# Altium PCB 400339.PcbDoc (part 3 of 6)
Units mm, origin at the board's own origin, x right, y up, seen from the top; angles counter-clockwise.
Board outline 146 x 63.5 mm, 4 copper layers (Top Layer, Mid-Layer 1, Mid-Layer 2, Bottom Layer), stack 1.505 mm thick; 400 components, 261 nets, 1523 pads, 1938 vias.
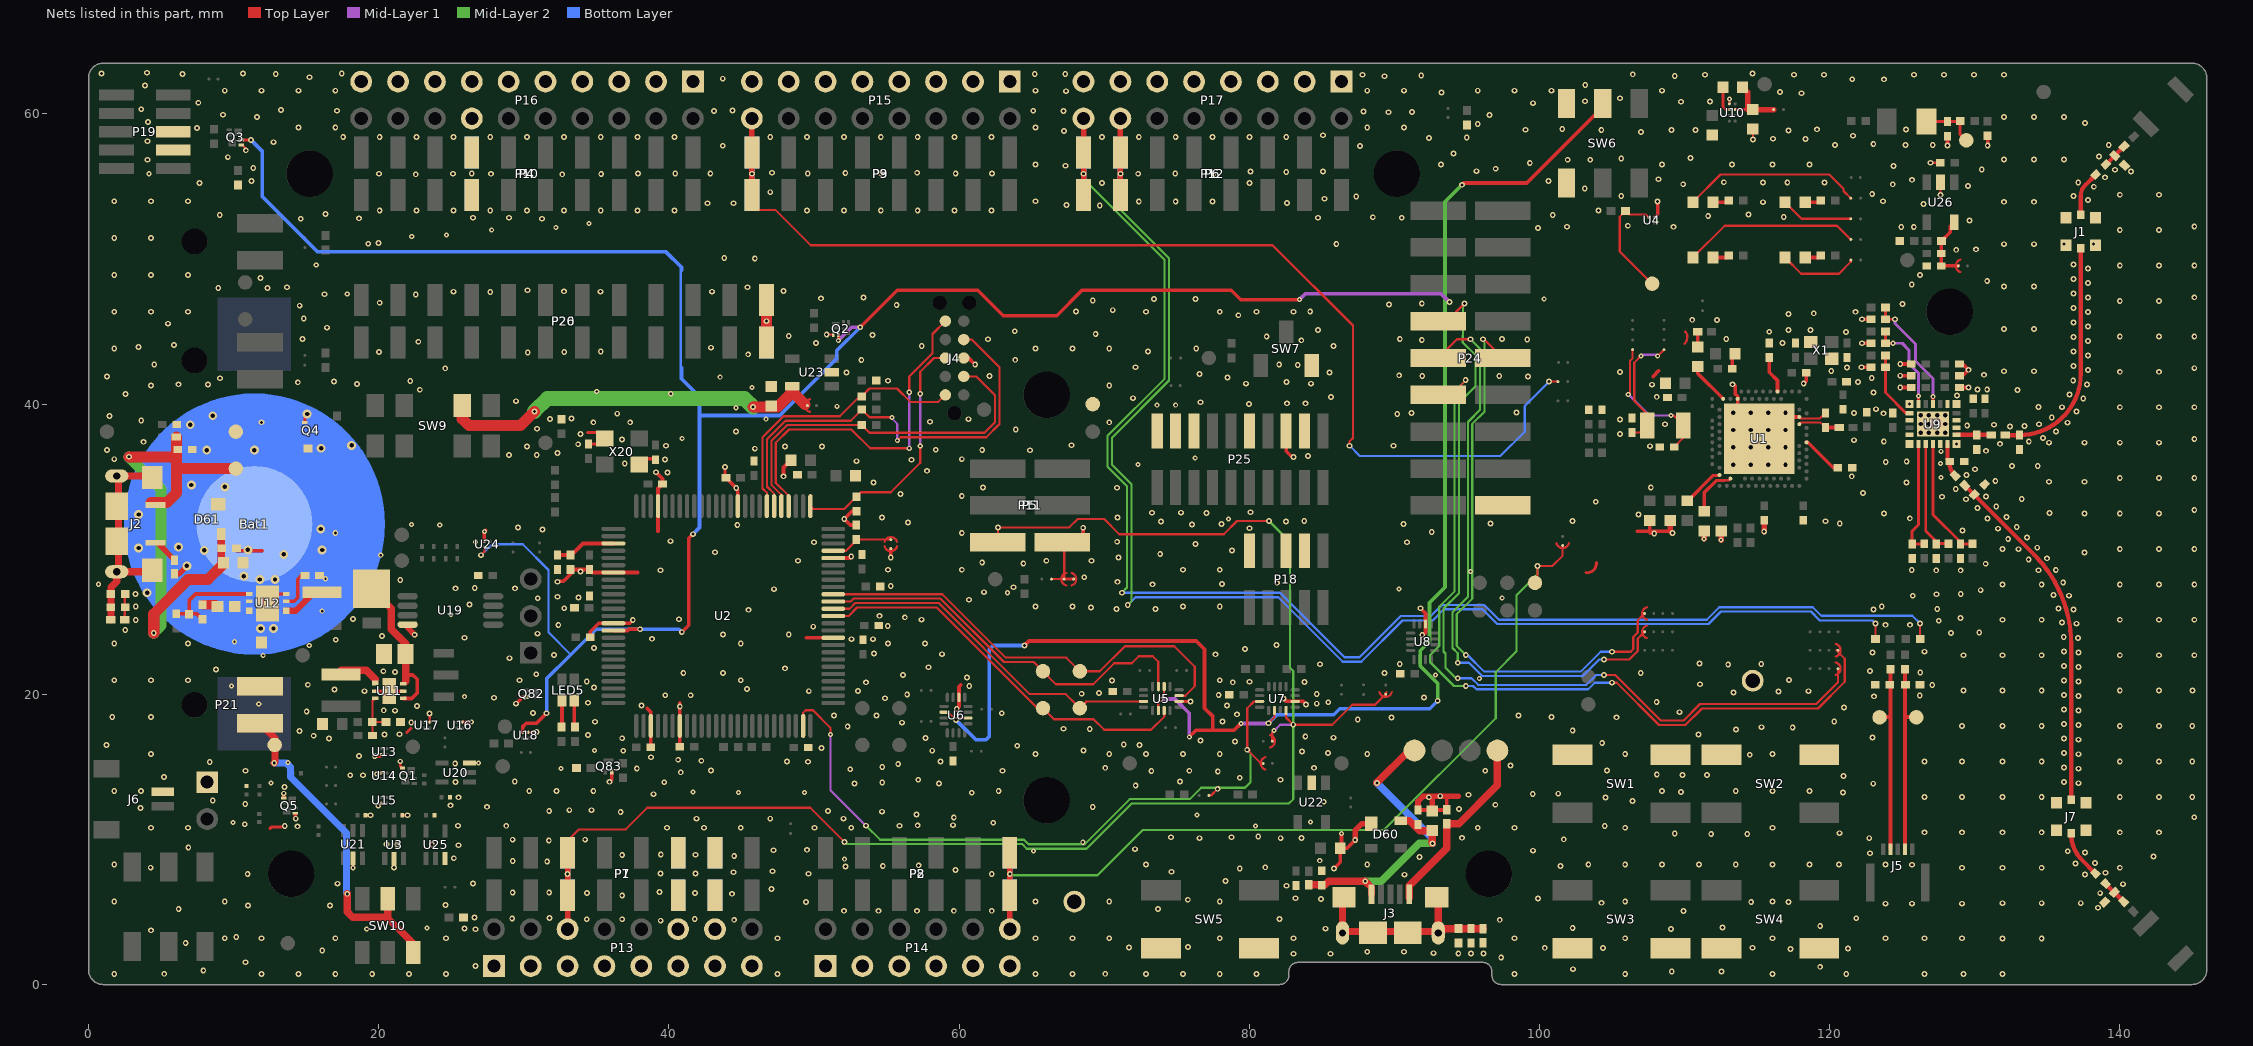
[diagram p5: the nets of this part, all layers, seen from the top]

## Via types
v1: diameter 0.4, hole 0.2, Top Layer to Bottom Layer, tented both sides, 1691 vias
v2: diameter 0.35, hole 0.15, Top Layer to Mid-Layer 1, tented both sides, 184 vias
v3: diameter 0.61, hole 0.305, Top Layer to Bottom Layer, 24 vias
v4: diameter 0.61, hole 0.305, Top Layer to Bottom Layer, tented both sides, 16 vias
v5: diameter 0.5, hole 0.3, Top Layer to Bottom Layer, tented both sides, 12 vias
v6: diameter 0.35, hole 0.15, Top Layer to Mid-Layer 1, tented top, 8 vias
v7: diameter 0.4, hole 0.2, Top Layer to Mid-Layer 1, tented top, 2 vias
v8: diameter 0.35, hole 0.15, Top Layer to Bottom Layer, tented top, 1 vias

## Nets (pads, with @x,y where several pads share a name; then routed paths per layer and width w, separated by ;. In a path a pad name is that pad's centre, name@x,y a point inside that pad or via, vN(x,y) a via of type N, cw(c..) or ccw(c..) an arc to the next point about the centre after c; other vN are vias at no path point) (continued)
GND: Bat1.2 C1.2 C2.2 C3.1 C4.1 C5.2 C6.2 C7.2 C8.2 C9.2 C10.1 C11.2 C12.2 C13.2 C14.2 C15.1 C16.2 C17.1 C18.1 C19.2 C20.2 C21.2 C22.2 C23.1 C24.1 C25.1 C26.1 C27.1 C28.1 C29.2 C30.2 C31.1 C32.2 C33.1 C34.1 C35.1 C36.1 C37.1 C38.1 C39.1 C40.1 C41.1 C42.1 C43.1 C44.1 C45.1 C46.2 C47.1 C48.1 C50.1 C51.1 C52.2 C53.1 C54.1 C55.1 C56.1 C57.1 C58.1 C59.1 C60.1 C61.1 C62.1 C63.2 C64.1 C65.1 C66.1 C67.1 C68.1 C69.1 C70.1 C71.1 C72.1 C73.1 C74.1 C75.1 C76.1 C77.1 C78.1 C79.1 C80.1 C82.1 C83.1 C84.1 C85.1 C86.1 C88.1 C89.1 C90.1 C91.1 C92.1 C93.1 C94.1 C95.1 C96.1 C97.1 C99.1 C103.1 D60.1 D61.1 FB62.2 FB63.2 FB64.2 FB65.2 J1.2 J4.3 J6.1 J7.2 L6.1 L7.1 P1.6 P1.7 P4.7 P7.6 P7.7 P10.7 P13.1 P13.3 P13.5 P13.7 P13.9 P13.11 P13.12 P13.13 P13.14 P13.15 P14.1 P14.3 P14.5 P14.7 P14.9 P14.11 P15.1 P15.3 P15.5 P15.7 P15.9 P15.11 P15.13 P15.15 P16.1 P16.3 P16.5 P16.7 P16.9 P16.11 P16.13 P16.14 P16.15 P16.17 P16.19 P17.1 P17.3 P17.5 P17.7 P17.9 P17.11 P17.13 P17.15 P18.3 P18.5 P18.9 P19.3 P19.5 P21.1 P24.18 P25.3 P25.5 P25.9 P25.15 P25.17 P25.19 P27.1 Q1.1 Q2.1 Q3.1 Q4.1 Q5.1 Q5.4 Q82.2 Q83.2 R14.1 R16.1 R23.1 R25.1 R26.2 R27.1 R30.1 R40.2 R62.1 R63.1 R67.2 R81.1 R84.1 R85.2 R88.2 R92.2 R94.2 SB30.2 SB32.1 SW1.1 SW2.1 SW3.1 SW4.1 SW5.1 SW6.1 SW6.4 SW7.1 TP12.1 TP39.1 TP40.1 TP41.1 U1.74 U1.B7 U1.F23 U2.3 U2.7 U2.35 U2.46 U2.61 U2.72 U2.82 U2.89 U3.2 U4.B1 U5.6 U6.6 U7.6 U8.6 U9.1 U9.5 U9.7 U9.9 U9.10 U9.12 U9.13 U9.18 U9.20 U9.22 U9.23 U10.A1 U11.2 U11.5 U11.7 U12.4 U12.8 U12.9 U12.11 U13.B1 U14.B1 U15.B1 U16.B1 U17.B1 U18.B1 U19.4 U20.3 U21.2 U22.2 U23.2 U24.B1 U25.3 U26.2 X1.2 X1.4 X20.2 X20.4 | length 107.3
  Top Layer w0.145: Q3.1@10.527,57.854 10.61,57.854 10.843,57.621 v1(10.843,57.494) ; v1(50.876,44.805) Q2.1@51.327,44.805 ; U1.F23@117.914,39.117 118.019,39.012 119.335,39.012 C3.1@119.715,39.393 ; U9.23@127.128,38.63 U9.23@127.378,38.63
  Top Layer w0.152: 110.008,44.16 ccw(c109.573,44.595) 110.189,44.595 110.189,44.675 ccw(c109.743,44.675) 110.058,44.99 ; U10.A1@113.097,60.7 v2(113.097,61.032) ; v1(114.717,58.242) C96.1@114.717,58.952 ; v1(126.949,56.635) C97.1@127.631,56.635 ; v1(127.648,54.414) U26.2@127.648,55.292
  Top Layer w0.203: FB65.2@2.496,25.139 2.496,26.867 R63.1@2.528,26.899 ; U12.11@12.344,25.984 U12.11@12.994,26.634 ; 12.498,10.738 12.602,10.843 13.316,10.843 ; U12.11@12.994,26.914 U12.4@13.614,26.914 ; Q4.1@14.909,38.747 14.909,39.166 v3(15.062,39.319) ; v3@15.047,39.385 v3@15.062,39.37 ; v2(18.23,8.048) 18.237,8.055 U21.2@18.237,8.702 ; C89.1@19.105,11.664 v1(19.431,11.664) ; v2(19.848,14.5) 19.924,14.576 U14.B1@20.171,14.576 ; v6(19.967,12.296) U15.B1@20.171,12.5 ; v1(21.065,8.07) U3.2@21.065,8.694 ; v8(21.487,15.382) 21.487,15.065 Q1.1@21.64,14.911 ; C103.1@21.621,11.664 v1(21.993,11.664) ; 21.935,17.361 22.231,17.656 ; U17.B1@23.517,18.082 v1@23.517,18.691 ; U16.B1@25.778,18.082 v2(26.387,18.082) ; U18.B1@30.319,17.386 30.859,17.386 v1(30.884,17.412) ; 34.392,38.049 35.145,38.049 X20.2@35.575,37.619 35.21,37.254 C29.2@34.458,37.254 ; 103.207,28.382 ccw(c103.276,29.032) 103.927,29.1
  Top Layer w0.229: v1(43.866,35.67) 43.866,34.999 C34.1@43.94,34.925 ; v1(55.296,29.436) SB30.2@55.296,30.045 ; U5.6@75.157,19.507 v1(75.946,19.507)
  Top Layer w0.25: U11.2@19.751,20.218 U11.7@20.726,20.218 U11.5@21.701,20.218 ; U24.B1@27.283,30.553 v2(27.283,31.22) v2@27.381,31.318 ; v1(82.372,19.71) 82.572,19.51 U7.6@83.165,19.51 83.715,19.51 v1(83.922,19.304) ; P25.5@82.55,38.145 82.55,36.754 v1@82.956,36.347 ; U4.B1@107.944,52.881 107.948,52.881 108.15,53.083 v1@108.15,53.997 ; 113.506,41.26 113.506,40.699 113.664,40.541 U1.B7@113.664,40.367 U1.74@113.664,39.117 ; U1.74@115.164,37.617 116.664,39.117 U1.F23@117.914,39.117
  Top Layer w0.254: C65.1@10.193,29.997 10.193,29.896 11.966,29.896 ; Q5.1@13.456,12.917 v2(13.456,13.178) ; Q5.4@14.257,11.751 14.257,11.455 v1(14.283,11.43) ; v1(29.464,19.355) 29.925,19.816 Q82.2@30.155,19.816 ; v1@32.451,27.788 32.731,27.788 33.289,28.346 33.289,28.608 C28.1@34.534,28.608 34.742,28.4 37.843,28.4 ; C25.1@34.604,23.9 C25.1@34.577,23.927 34.577,24.309 35.168,24.9 37.295,24.9 v1(37.516,25.121) ; v1(35.916,13.97) 36.064,14.119 Q83.2@36.064,14.687 ; X20.4@37.963,36.228 C30.2@39.081,36.228 ; 38.506,19.05 38.506,19.025 38.754,18.777 U2.3@38.754,17.825 ; C31.1@38.742,16.358 U2.3@38.742,17.813 ; v1(39.116,35.306) 39.555,34.867 C32.2@39.555,34.493 39.254,34.192 39.254,31.253 ; C33.1@40.75,16.383 40.754,16.388 U2.7@40.754,17.825 40.754,19.418 ; C34.1@43.94,34.925 v1@44.6,34.265 ; U2.61@44.754,32.975 v1@44.754,34.055 ; v1(47.904,35.027) 47.904,35.635 C38.1@48.413,36.144 ; 49.481,23.9 U2.35@51.329,23.9 ; U2.46@51.329,29.4 52.479,29.4 v1(52.568,29.489) ; C44.1@52.924,31.666 52.5,31.666 v1(52.085,32.08) 52.627,32.622 R67.2@52.924,32.622 ; v1(59.842,18.999) 59.992,19.148 U6.6@59.992,19.792 59.992,20.52 60.122,20.65 ; J4.3@60.325,43.18 60.655,43.18 v1(61.112,42.723) ; v1(85.852,8.001) 86.273,8.422 C91.1@86.273,9.398 ; v2(86.36,10.414) 86.36,9.485 C91.1@86.273,9.398 ; v1(87.303,9.953) 86.748,9.398 C91.1@86.273,9.398 ; C62.1@91.632,12.032 92.544,12.032 FB62.2@93.65,12.032 ; v1(91.796,25.933) 92.148,25.581 U8.6@92.148,24.847 92.148,24.254 v1@91.973,24.079 ; FB62.2@93.614,12.033 93.614,12.979 ; 106.756,31.242 v1@109.093,31.242 ; C6.2@107.613,31.992 107.613,31.168 107.664,31.117 ; 107.837,41.898 108.218,42.306 ; C16.2@113.301,42.443 113.301,43.294 C15.1@113.489,43.481 ; v1(118.214,41.417) 118.389,41.592 C12.2@118.389,42.167 ; v1(122.205,42.543) C59.1@122.856,42.543 ; v1(122.235,44.197) C55.1@122.856,44.197 ; v1(122.239,45.851) C74.1@122.856,45.851 ; v1@124.998,41.148 C54.1@125.628,41.148 ; v1@124.998,41.961 C53.1@125.628,41.961 ; v1@124.998,42.774 C23.1@125.628,42.774 ; v1(128.127,57.836) C94.1@128.127,58.475 ; C56.1@128.948,41.148 v1(129.578,41.148) ; C57.1@128.948,41.961 129.171,41.961 v1(129.578,42.367) 129.171,42.774 C58.1@128.948,42.774 ; v1(130.896,57.836) R14.1@130.896,58.5
  Top Layer w0.305: v1(19.725,15.747) 20.065,15.747 U13.B1@20.134,15.816
  Top Layer w0.381: FB63.2@5.933,28.304 6.231,28.304 v3(6.782,28.854) ; U19.4@21.993,24.806 21.993,24.591 v1(22.479,24.105) ; v1(87.303,9.953) 87.303,10.62 87.772,11.09 D60.1@88.402,11.09 ; C62.1@91.632,12.032 91.632,12.613 91.999,12.979 94.412,12.979 ; C61.1@92.544,12.032 C61.1@92.623,11.953 92.623,12.979 ; C19.2@109.014,31.992 109.014,31.267 v1(109.164,31.117) ; v2@111.364,30.709 C20.2@111.364,31.267 ; v2@112.539,30.632 C21.2@112.539,31.267 ; C7.2@115.49,31.992 115.49,31.221 v1(115.494,31.217)
  Top Layer w0.635: R81.1@7.899,26.179 C83.1@8.76,26.179
  other v1: 1.772,0.723 11.932,0.723 14.472,0.723 17.012,0.723 19.552,0.723 22.092,0.723 24.632,0.723 47.492,0.723 65.272,0.723 67.812,0.723 72.892,0.723 75.432,0.723 77.972,0.723 80.512,0.723 98.292,0.723 105.912,0.723 116.072,0.723 121.152,0.723 126.539,0.723 129.232,0.723 131.926,0.723 5.223,0.737 70.079,0.737 109.123,0.889 112.548,0.889 7.912,0.959 102.311,1.057 119.351,1.219 26.67,1.27 10.82,1.532 97.366,1.862 83.052,2.12 85.592,2.12 94.412,2.134 95.275,2.134 96.139,2.134 92.71,2.159 88.138,2.261 90.678,2.261 16.109,2.351 117.297,2.455 121.276,2.491 100.37,2.528 104.394,2.519 114.687,2.532 71.717,2.541 75.771,2.592 6.696,2.87 131.926,3.165 134.619,3.165 9.392,3.187 11.932,3.187 17.012,3.187 24.632,3.187 47.492,3.187 65.272,3.187 67.812,3.187 70.352,3.187 77.972,3.187 83.052,3.187 98.292,3.187 105.912,3.187 116.072,3.187 123.845,3.187 126.539,3.187 129.129,3.187 10.185,3.277 4.309,3.734 26.67,3.81 109.076,3.83 25.908,3.855 85.261,3.847 102.295,3.886 112.618,3.932 119.352,4.023 39.434,4.4 44.501,4.458 97.265,4.458 34.342,4.496 36.783,4.496 41.783,4.521 82.093,4.521 29.201,4.555 121.837,4.569 31.775,4.587 26.596,4.623 109.932,5.066 52.07,5.08 54.458,5.08 57.099,5.08 59.639,5.08 62.255,5.08 6.214,5.207 73.707,5.207 138.507,5.288 10.998,5.436 16.639,5.436 24.613,5.486 123.845,5.57 125.674,5.57 129.129,5.57 131.926,5.606 134.619,5.606 137.313,5.606 104.277,5.629 114.598,5.679 49.454,5.69 117.159,5.69 1.772,5.727 9.392,5.727 65.272,5.727 70.352,5.727 77.972,5.727 105.912,5.727 116.072,5.727 75.768,5.842 84.938,5.893 99.898,5.918 83.185,5.944 36.783,6.134 44.348,6.248 138.65,6.294 34.347,6.315 41.808,6.299 29.235,6.35 31.75,6.35 39.345,6.375 47.07,6.592 82.57,6.807 140.215,6.916 17.152,6.948 26.492,6.96 78.365,7.128 90.703,7.569 137.614,7.589 62.255,7.612 10.97,7.62 49.622,7.637 39.423,7.658 41.83,7.658 139.023,7.702 44.45,7.736 74.651,7.772 47.142,7.807 59.757,7.897 79.347,7.989 129.129,8.048 131.926,8.048 134.619,8.048 140.006,8.048 4.283,8.052 81.102,8.077 52.179,8.125 54.746,8.178 101.454,8.178 57.218,8.215 1.772,8.267 72.892,8.267 88.132,8.267 103.372,8.267 105.912,8.267 108.452,8.267 110.992,8.267 113.532,8.267 116.072,8.267 118.612,8.267 120.651,8.267 123.845,8.267 125.674,8.255 136.954,8.34 138.292,8.384 31.613,8.47 29.237,8.503 25.178,8.702 91.737,8.788 142.327,8.825 44.501,8.865 36.783,8.928 41.834,8.941 39.446,8.966 122.778,9.046 137.595,9.1 136.414,9.182 99.568,9.226 47.221,9.253 49.516,9.282 72.126,9.328 6.879,9.449 25.502,9.597 21.291,9.643 20.547,9.665 23.667,9.652 31.725,9.931 29.235,9.982 34.232,9.982 101.676,10.008 76.581,10.084 82.169,10.084 83.606,10.092 122.733,10.084 94.666,10.109 74.602,10.152 78.775,10.152 80.625,10.196 111.839,10.373 114.328,10.373 109.327,10.406 120.679,10.429 126.539,10.489 129.129,10.489 131.926,10.489 134.619,10.489 140.006,10.489 142.7,10.489 4.312,10.807 6.852,10.807 39.872,10.807 42.412,10.807 44.952,10.807 50.032,10.807 52.572,10.807 95.752,10.807 98.292,10.807 105.912,10.807 116.072,10.807 14.394,10.903 13.524,10.922 25.469,10.943 28.794,10.935 55.904,10.943 104.504,10.922 57.15,10.973 59.588,10.981 10.766,11.045 62.357,11.151 41.91,11.43 46.99,11.43 52.032,11.43 59.639,11.506 145.134,11.528 57.074,11.709 36.678,11.897 54.686,11.913 50.962,11.955 31.75,11.963 33.138,12.015 34.668,12.015 94.463,12.09 3.581,12.167 27.473,12.247 69.215,12.243 24.949,12.35 96.964,12.39 10.799,12.449 106.417,12.639 8.56,12.675 25.491,12.9 104.546,12.886 92.38,12.903 126.539,12.931 129.129,12.931 131.926,12.931 134.619,12.931 140.006,12.931 142.7,12.931 145,12.931 93.167,12.979 95.123,13.081 38.938,13.117 99.543,13.132 101.298,13.152 60.872,13.217 120.929,13.233 109.763,13.259 30.376,13.333 1.772,13.347 3.607,13.335 32.252,13.347 34.792,13.347 62.732,13.347 108.452,13.347 113.532,13.347 116.072,13.347 118.612,13.347 13.507,13.62 72.174,13.71 52.801,13.862 58.616,13.862 123.012,13.843 137.15,13.876 39.682,13.939 54.707,13.927 25.293,13.96 136.158,13.949 29.379,13.995 75.219,13.995 57.191,14.112 82.149,14.115 79.35,14.249 5.207,14.3 120.969,14.379 18.043,14.425 18.923,14.423 109.87,14.434 111.558,14.434 108.092,14.468 40.817,14.625 77.836,14.674 73.254,14.707 10.82,14.732 42.901,14.742 62.992,14.732 75.87,14.732 96.266,14.732 104.659,14.749 52.502,14.834 137.15,14.876 37.792,14.894 70.079,14.935 84.455,14.935 136.158,14.949 54.707,14.982 98.01,15.089 55.804,15.189 25.273,15.24 8.357,15.342 49.589,15.352 48.133,15.367 58.725,15.367 126.539,15.372 129.129,15.372 131.926,15.372 134.619,15.372 140.006,15.372 142.7,15.372 145,15.372 42.236,15.419 40.64,15.494 38.772,15.666 18.646,15.747 114.499,15.837 4.312,15.887 65.272,15.887 70.352,15.887 72.892,15.887 75.432,15.887 77.972,15.887 88.132,15.887 105.912,15.887 116.072,15.887 137.15,15.876 136.158,15.949 85.429,15.957 83.639,16.062 36.854,16.111 58.152,16.117 68.58,16.129 50.521,16.307 64.009,16.455 1.245,16.51 72.441,16.51 71.349,16.535 104.327,16.636 79.019,16.739 76.649,16.819 137.15,16.876 16.569,16.952 136.158,16.949 36.783,16.972 57.683,16.993 85.814,17.014 122.961,17.018 83.867,17.094 15.519,17.145 34.418,17.207 20.392,17.234 110.973,17.221 21.438,17.252 14.539,17.469 102.295,17.504 113.54,17.577 69.006,17.612 67.208,17.628 117.456,17.704 115.311,17.735 52.324,17.78 129.129,17.822 131.926,17.822 134.619,17.822 140.006,17.822 142.7,17.822 145,17.822 137.15,17.876 136.158,17.949 56.059,18.046 22.245,18.064 34.9,18.11 78.168,18.128 120.32,18.136 87.482,18.256 89.798,18.399 1.638,18.427 4.312,18.427 100.832,18.427 105.308,18.415 51.384,18.542 54.305,18.542 98.552,18.542 79.156,18.62 23.499,18.673 62.941,18.694 30.632,18.72 109.662,18.77 15.037,18.821 21.133,18.872 137.15,18.876 20.345,18.898 136.158,18.949 120.993,19.095 40.754,19.152 22.649,19.201 38.115,19.228 78.461,19.228 84.654,19.355 34.435,19.418 85.446,19.456 108.085,19.476 54.895,19.73 27.94,19.761 92.05,19.787 123.063,19.863 137.15,19.876 126.214,19.91 39.751,19.939 41.504,19.939 77.894,19.959 136.158,19.949 56.425,19.992 84.654,20.013 68.453,20.041 69.647,20.091 113.386,20.117 116.475,20.186 19.025,20.218 49.647,20.218 53.035,20.235 118.542,20.218 129.232,20.255 131.926,20.255 134.619,20.255 140.006,20.255 142.7,20.255 145.018,20.255 16.955,20.331 45.392,20.365 34.849,20.472 60.706,20.574 127.079,20.643 15.116,20.662 111.071,20.692 53.594,20.828 78.867,20.828 80.021,20.864 83.82,20.853 137.15,20.876 34.342,20.884 136.158,20.949 1.772,20.967 4.312,20.967 6.852,20.967 29.712,20.967 44.952,20.967 70.536,20.955 77.972,20.967 117.204,20.983 60.557,21.164 56.134,21.336 30.861,21.387 40.996,21.463 43.739,21.463 89.332,21.463 106.985,21.463 126.251,21.506 21.133,21.539 20.32,21.59 122.784,21.615 8.787,21.721 48.006,21.793 57.898,21.863 137.15,21.876 136.158,21.949 113.013,22.062 84.887,22.073 115.291,22.094 90.373,22.098 111.029,22.118 29.025,22.491 129.232,22.697 131.926,22.697 134.619,22.697 140.006,22.697 142.7,22.697 145.141,22.697 32.08,22.708 58.829,22.766 77.673,22.758 54.137,22.809 137.15,22.876 122.95,22.892 126.539,22.939 136.158,22.949 79.705,23.114 34.839,23.19 81.871,23.399 1.772,23.507 6.852,23.507 44.952,23.507 55.112,23.507 57.652,23.507 17.042,23.763 52.593,23.8 54.059,23.8 38.837,23.825 137.128,23.876 25.908,23.901 136.143,23.949 20.218,24.028 91.923,24.079 43.739,24.13 48.26,24.13 30.937,24.181 128.365,24.23 130.315,24.262 2.53,24.425 49.952,24.663 55.088,24.704 32.382,24.775 123.845,24.79 125.534,24.79 137.028,24.871 136.026,24.942 127.523,25.072 3.257,25.131 131.926,25.138 134.619,25.138 140.006,25.138 142.7,25.138 145.141,25.138 57.404,25.146 40.691,25.171 18.22,25.197 129.028,25.266 56.262,25.308 54.526,25.41 45.494,25.826 123.02,25.849 136.821,25.849 70.843,25.885 73.533,25.883 127.424,25.886 135.787,25.913 32.791,25.933 69.086,25.984 3.255,26.043 65.272,26.047 67.812,26.047 75.432,26.047 77.972,26.047 123.596,26.06 26.264,26.187 60.681,26.518 30.963,26.619 33.772,26.67 32.33,26.725 125.73,26.797 136.511,26.8 135.425,26.846 3.245,26.914 127.379,26.899 129.039,26.919 61.717,27.039 130.415,27.178 47.246,27.248 25.298,27.305 29.388,27.305 26.619,27.331 63.754,27.379 55.296,27.457 73.339,27.583 131.926,27.58 134.619,27.58 140.006,27.58 142.7,27.58 145.141,27.58 78.113,27.611 81.915,27.686 136.101,27.712 70.929,27.755 32.324,27.762 21.488,27.889 68.631,28.067 33.899,28.473 127.354,28.547 129.037,28.547 39.421,28.55 125.665,28.559 134.39,28.553 135.593,28.573 55.112,28.587 60.192,28.587 75.432,28.587 77.972,28.587 130.758,29.001 64.43,29.007 61.595,29.083 48.895,29.21 66.015,29.21 69.127,29.21 133.723,29.298 134.993,29.373 70.993,29.439 73.863,29.667 137.565,29.769 43.18,29.794 78.816,29.921 131.926,30.021 133.016,30.005 140.006,30.021 142.7,30.021 145.141,30.021 134.315,30.109 76.302,30.37 50.013,30.48 90.881,30.48 70.9,30.515 40.107,30.556 132.308,30.712 133.608,30.816 107.918,31.092 17.012,31.127 60.192,31.127 92.583,31.191 129.152,31.293 31.293,31.369 131.601,31.419 80.01,31.448 29.591,31.496 132.901,31.523 44.719,31.674 76.062,31.708 78.094,31.734 90.627,31.75 120.705,31.765 96.622,31.775 56.49,31.852 73.914,31.902 82.525,31.902 119.71,31.928 83.795,31.953 102.286,31.953 130.894,32.126 125.53,32.131 54.686,32.182 70.917,32.182 132.194,32.23 106.832,32.385 123.749,32.472 137.565,32.463 140.006,32.463 142.7,32.463 77.064,32.501 135.164,32.501 73.302,32.513 75.306,32.521 80.09,32.549 145.141,32.715 130.187,32.833 131.487,32.937 103.886,33.274 129.396,33.445 133.246,33.472 127.758,33.619 130.78,33.644 60.192,33.667 55.956,33.807 122.301,33.884 128.699,34.162 44.643,34.214 70.891,34.239 107.68,34.258 61.646,34.265 125.298,34.59 54.102,34.595 135.123,34.652 137.565,34.652 131.425,34.703 140.006,34.904 142.7,34.904 145.141,34.904 121.531,35.027 129.436,35.111 39.903,35.286 57.785,35.403 130.026,35.515 132.575,35.729 134.347,35.729 36.957,35.916 123.872,36.017 125.315,36.051 52.934,36.068 39.737,36.191 56.718,36.17 1.772,36.207 60.192,36.207 83.052,36.364 84.049,36.424 28.99,36.491 30.897,36.491 32.332,36.624 130.778,36.782 64.893,36.821 1.27,36.83 61.595,36.83 58.395,36.855 45.923,36.932 30.226,37.084 47.996,37.084 50.546,37.084 107.63,37.103 39.802,37.135 89.947,37.135 67.759,37.17 33.749,37.233 128.753,37.255 131.747,37.267 135.123,37.346 137.565,37.346 140.006,37.346 142.7,37.346 3.799,37.405 123.739,37.416 133.734,37.423 121.689,37.517 36.769,37.567 145.141,37.598 134.703,37.67 33.899,37.948 105.562,37.948 135.601,38.109 44.628,38.125 63.906,38.261 30.906,38.306 132.441,38.466 133.441,38.487 129.483,38.532 131.325,38.583 108.664,38.617 134.433,38.616 136.389,38.725 11.932,38.747 34.792,38.747 37.332,38.747 70.352,38.747 57.988,38.786 3.636,38.877 105.562,38.938 31.801,38.976 60.655,38.964 33.298,39.002 135.313,39.09 1.448,39.192 90.2,39.327 36.443,39.345 123.714,39.367 91.186,39.395 121.681,39.395 98.425,39.421 137.02,39.501 123.19,39.654 136.026,39.792 140.006,39.787 142.7,39.787 145.141,39.787 134.392,39.805 79.985,40.005 125.503,40.005 82.601,40.056 83.871,40.056 76.632,40.132 29.464,40.206 137.482,40.387 71.984,40.411 85.641,40.492 108.087,40.506 128.786,40.589 136.529,40.656 2.54,40.691 123.02,40.798 132.96,40.975 22.835,40.996 130.2,41.008 130.861,41.008 124.871,41.148 4.312,41.287 70.352,41.287 107.764,41.342 6.201,41.368 8.238,41.353 113.313,41.368 137.742,41.353 18.503,41.395 79.776,41.41 84.267,41.41 14.427,41.504 121.964,41.517 82.572,41.529 16.916,41.554 22.172,41.587 55.109,41.61 136.791,41.621 9.068,41.783 122.908,41.811 78.494,41.837 99.212,41.896 1.27,41.91 62.103,41.935 91.923,41.935 97.234,41.942 90.335,41.985 124.871,41.961 130.635,42.02 76.577,42.088 85.527,42.182 52.248,42.189 105.562,42.215 140.006,42.228 142.7,42.228 132.026,42.268 134.096,42.268 120.114,42.292 137.809,42.351 24.587,42.469 145.141,42.481 121.194,42.517 72.154,42.541 136.816,42.621 83.346,42.698 4.531,42.728 82.064,42.74 124.871,42.774 53.264,43.053 63.876,43.056 137.809,43.351 45.466,43.434 30.277,43.561 20.015,43.586 32.791,43.586 73.026,43.627 136.816,43.621 35.306,43.637 1.772,43.827 65.272,43.827 67.812,43.827 70.352,43.827 76.35,43.827 42.901,43.891 3.454,43.942 85.814,44.005 57.429,44.018 5.893,44.069 116.757,44.212 50.14,44.221 22.733,44.298 137.809,44.351 83.591,44.399 91.897,44.423 99.162,44.45 62.001,44.475 90.379,44.488 14.757,44.501 97.426,44.501 112.878,44.501 136.816,44.621 81.204,44.653 140.006,44.67 142.7,44.67 145.141,44.67 48.26,44.704 54.042,44.759 69.416,44.834 121.127,44.981 115.845,44.992 63.843,45.024 84.749,45.11 117.164,45.117 118.694,45.11 132.026,45.187 134.096,45.187 16.43,45.271 137.809,45.351 5.479,45.546 136.816,45.621 110.538,45.811 112.243,45.801 14.832,45.894 79.248,46.126 117.159,46.223 118.91,46.261 137.809,46.351 1.772,46.367 4.312,46.367 6.852,46.367 72.892,46.367 77.972,46.367 80.512,46.367 83.052,46.367 121.787,46.362 68.066,46.38 84.201,46.38 70.595,46.476 136.816,46.621 14.554,46.787 55.702,46.838 89.637,46.863 125.028,46.893 91.897,46.94 20.066,46.99 140.006,47.111 142.7,47.111 69.215,47.142 73.431,47.244 76.302,47.244 50.495,47.295 53.416,47.356 137.809,47.351 145.141,47.363 22.555,47.549 16.256,47.574 136.816,47.621 27.686,47.727 25.146,47.752 35.281,47.752 42.977,47.752 32.766,47.777 47.904,47.803 30.251,47.854 8.944,48.016 12.344,48.006 13.678,48.057 45.415,48.057 132.026,48.107 134.096,48.107 125.664,48.245 137.809,48.351 130.861,48.486 136.816,48.621 11.862,48.692 1.772,48.907 4.312,48.907 6.852,48.907 126.232,48.907 137.809,49.351 140.006,49.553 142.7,49.553 145.141,49.553 136.816,49.621 45.923,50.038 43.815,50.063 128.729,50.638 130.082,50.671 132.026,51.026 134.096,51.026 136.165,51.026 138.203,51.026 86.004,51.029 19.28,51.054 19.99,51.105 1.772,51.447 4.312,51.447 140.006,51.994 142.7,51.994 99.898,52.146 124.94,52.207 125.806,52.219 101.898,52.225 109.245,52.222 145.141,52.246 106.096,52.299 129.64,52.652 14.63,52.781 31.262,52.781 18.644,52.807 26.497,52.85 28.99,52.85 84.749,52.85 90.514,52.85 88.519,52.883 116.84,52.908 111.633,52.959 9.042,53.035 100.924,53.042 114.414,53.075 16.332,53.111 20.066,53.34 22.606,53.34 25.146,53.34 27.686,53.34 30.226,53.34 32.766,53.34 35.306,53.34 37.846,53.34 40.386,53.34 49.53,53.34 52.07,53.34 54.61,53.34 57.15,53.34 59.69,53.34 62.23,53.34 104.064,53.34 69.695,53.691 67.4,53.721 126.483,53.785 42.672,53.848 44.45,53.848 82.601,53.858 115.414,53.921 132.026,53.945 134.096,53.945 1.772,53.987 4.312,53.987 6.852,53.987 65.272,53.987 72.39,53.975 74.93,53.975 77.47,53.975 108.15,53.975 123.692,53.987 137.809,54.073 85.19,54.159 87.376,54.305 136.816,54.338 105.639,54.356 140.006,54.436 142.7,54.436 122.936,54.483 46.99,54.61 103.124,54.864 138.215,54.987 129.54,55.037 109.911,55.154 124.356,55.152 7.645,55.245 69.85,55.245 80.01,55.245 112.711,55.292 115.414,55.286 117.089,55.28 119.649,55.286 137.141,55.284 11.227,55.372 100.635,55.372 125.69,55.462 108.204,55.499 138.978,55.633 22.555,55.842 32.65,55.842 27.749,55.875 30.155,55.875 35.336,55.859 20.031,55.88 25.119,55.88 26.416,55.89 37.864,55.89 54.615,55.89 59.766,55.89 72.348,55.88 77.544,55.88 40.436,55.906 42.857,55.906 49.57,55.906 62.272,55.906 74.902,55.906 47.112,55.946 52.16,55.939 57.113,55.946 82.55,55.998 80.09,56.045 85.09,56.034 95.671,56.057 140.783,56.034 139.678,56.156 130.486,56.168 96.988,56.222 11.354,56.286 124.415,56.412 67.337,56.43 113.282,56.514 65.272,56.527 93.212,56.527 108.452,56.527 116.072,56.527 118.612,56.527 99.339,56.617 4.072,56.843 101.949,56.845 103.505,56.845 132.026,56.865 134.096,56.865 136.165,56.865 105.639,56.931 110.413,56.964 9.601,57.023 138.577,57.075 94.071,57.276 87.63,57.785 43.713,57.81 120.374,57.852 127.113,57.852 139.244,57.856 125.23,57.867 123.015,57.93 12.749,58.056 4.072,58.123 118.336,58.278 116.107,58.295 92.386,58.352 94.993,58.384 17.551,58.42 20.066,58.42 22.606,58.42 25.146,58.42 27.686,58.42 30.226,58.42 32.766,58.42 35.306,58.42 37.846,58.42 40.386,58.42 46.99,58.42 49.53,58.42 52.07,58.42 54.61,58.42 57.15,58.42 59.69,58.42 62.23,58.42 69.85,58.42 72.39,58.42 74.93,58.42 77.47,58.42 80.01,58.42 82.55,58.42 121.62,58.5 85.085,58.532 107.01,58.75 67.24,58.826 117.175,58.853 104.267,58.889 109.111,58.889 110.752,58.897 99.04,58.913 119.128,58.941 125.272,58.928 101.576,58.971 7.467,59.03 14.472,59.067 17.012,59.067 65.272,59.067 88.132,59.067 90.672,59.067 95.752,59.305 137.595,59.383 4.09,59.455 132.026,59.784 134.096,59.784 136.165,59.784 11.608,59.792 96.558,59.939 9.271,59.944 89.608,60.122 91.215,60.14 87.884,60.163 43.11,60.196 67.208,60.196 17.12,60.222 65.113,60.222 44.377,60.241 13.273,60.266 3.636,60.328 99.568,60.744 7.57,60.776 109.768,60.843 103.146,60.875 111.762,60.87 105.562,61.087 118.064,61.426 93.247,61.483 116.585,61.505 67.369,61.573 9.392,61.607 11.932,61.607 14.472,61.607 17.012,61.607 65.272,61.607 88.132,61.607 90.672,61.607 95.752,61.607 98.292,61.607 100.832,61.607 108.452,61.607 3.886,61.968 103.161,61.992 121.564,62.393 123.749,62.388 43.713,62.433 15.231,62.53 89.318,62.6 109.327,62.615 91.855,62.643 87.808,62.704 111.408,62.704 117.541,62.704 119.611,62.704 125.818,62.704 127.888,62.704 129.957,62.704 132.026,62.704 106.436,62.733 6.477,62.763 12.902,62.763 65.218,62.763 67.322,62.763 0.889,62.789 10.647,62.788 17.456,62.795 114.687,62.789 4.04,62.84
  other v2: 19.177,3.835 23.325,3.886 84.861,8.534 52.095,8.636 65.126,9.195 68.529,9.804 80.442,10.922 9.957,11.176 84.226,11.201 76.403,11.684 85.141,12.598 44.806,13.233 49.352,13.233 41.656,13.259 12.573,13.894 32.563,14.884 26.873,15.265 13.741,15.291 34.874,16.129 11.735,19.329 25.908,19.837 9.855,20.574 95.86,21.082 92.837,21.336 12.04,22.682 15.215,23.368 10.058,23.622 24.994,25.502 16.104,25.73 97.434,26.634 63.348,27 90.322,27.254 0.686,27.584 16.332,27.965 95.25,28.473 20.142,29.591 26.68,30.505 112.522,30.632 111.354,30.709 24.206,31.674 22.25,31.699 78.562,32.08 72.339,35.839 76.276,36.297 40.919,37.643 46.685,38.964 44.628,39.751 51.587,39.853 73.635,39.929 74.93,39.929 40.132,40.716 35.027,40.869 45.72,41.148 43.536,41.859 100.33,47.244 17.831,47.6 15.697,49.581 22.276,51.562 24.663,51.664 27.788,51.994 32.207,52.172 34.493,52.451 4.166,55.88
  other v3: 11.862,24.536 12.751,24.536 4.039,27 11.811,27.915 12.852,27.915 10.708,28.144 13.452,29.642 7.976,29.921 10.988,29.959 16.104,29.947 3.454,30.084 6.212,30.151 16.002,31.394 3.454,32.395 9.398,34.3 7.087,34.427 8.153,36.83 11.43,36.83 16.027,36.957 18.136,37.16 7.01,38.583 8.56,39.202
  other v4: 113.364,35.817 114.564,35.817 115.764,35.817 116.964,35.817 113.364,37.017 114.564,37.017 115.764,37.017 116.964,37.017 113.364,38.217 114.564,38.217 115.764,38.217 116.964,38.217 113.364,39.417 114.564,39.417 115.764,39.417 116.964,39.417
  other v5: 126.278,38.03 126.845,38.03 127.411,38.03 127.977,38.03 126.278,38.63 126.845,38.63 127.411,38.63 127.977,38.63 126.278,39.23 126.845,39.23 127.411,39.23 127.977,39.23
  other v6: 127.671,34.953 127.648,35.916 127.671,36.749
I\F\_\O\F\F\: Q2.2 Q3.2 SW6.2 U2.90 U5.2 U5.10 U6.2 U6.10 U7.2 U18.B2 U24.B2 | length 258.7
  Top Layer w0.152: v1(27.051,29.591) 27.283,29.823 U24.B2@27.283,30.153 ; U6.10@58.967,18.767 59.26,18.767 59.66,18.367 U6.2@60.617,18.367 ; U5.2@73.732,18.882 73.732,19.478 v2(73.907,19.653) 74.132,19.878 U5.10@74.132,20.532 ; v1(81.331,18.009) 81.74,18.418 U7.2@81.74,18.885
  Top Layer w0.203: Q3.2@10.527,58.204 v1(11.203,58.204) ; v2(51.677,44.386) Q2.2@51.677,44.805
  Top Layer w0.254: U18.B2@29.919,17.386 29.919,17.752 30.166,17.999 30.877,17.999 v1(31.572,18.694) ; U2.90@36.179,24.4 37.163,24.4 37.248,24.486 v1(38.024,24.486) ; v1(40.894,24.282) 41.377,24.765 41.377,30.759 v1(41.656,31.039) ; v1(53.188,45.303) 55.738,47.854 61.295,47.854 63.047,46.101 66.726,46.101 68.478,47.854 78.764,47.854 79.416,47.201 83.456,47.201 v2(83.469,47.214) ; v1(64.516,23.368) 64.823,23.675 76.35,23.675 76.913,23.112 76.913,19.048 77.495,18.466 77.495,17.533 ; v2(75.87,17.069) 76.327,17.526 77.128,17.526 77.135,17.533 77.495,17.533 ; v2(79.426,17.983) 78.976,17.533 77.495,17.533 ; v1(94.666,55.118) 94.793,55.245 99.129,55.245 SW6.2@104.369,60.484
  Mid-Layer 1 w0.254: v2(51.677,44.386) 52.594,45.303 v1(53.188,45.303) ; v2@73.932,19.678 74.886,19.678 75.87,18.694 v2(75.87,17.069) ; v2(79.426,17.983) 81.305,17.983 v1(81.331,18.009) ; v2(83.469,47.214) 83.854,47.6 93.243,47.6 v1(93.802,47.041)
  Mid-Layer 2 w0.254: v1(92.989,19.558) 92.989,20.752 91.796,21.946 91.796,23.004 92.431,23.639 92.431,26.309 93.497,27.376 93.497,47.041 ; v1(93.802,47.041) 93.497,47.041 ; v1(94.666,55.118) 93.497,53.95 93.497,47.041
  Bottom Layer w0.152: v1(27.051,29.591) 27.805,30.345 29.929,30.345 31.699,28.575 31.699,24.272 33.238,22.733 ; 40.818,42.52 40.818,49.224
  Bottom Layer w0.254: v1(11.203,58.204) 11.963,57.444 11.963,54.331 15.799,50.495 39.802,50.495 40.869,49.428 40.869,49.224 ; v1(31.572,18.694) 31.572,21.067 33.238,22.733 34.991,24.486 v1(38.024,24.486) 40.691,24.486 v1(40.894,24.282) ; 40.869,42.52 40.869,41.758 42.113,40.513 42.113,39.268 ; v1(41.656,31.039) 42.113,31.496 42.113,39.268 ; v1(53.188,45.303) 51.575,43.69 51.575,43.149 47.643,39.218 42.164,39.218 42.113,39.268 ; v1(59.792,18.237) 61.163,16.866 61.849,16.866 62.078,17.094 62.078,23.089 62.357,23.368 v1(64.516,23.368) ; v1(81.331,18.009) 81.915,18.593 85.827,18.593 86.245,19.011 92.443,19.011 v1(92.989,19.558)
IMCU_BOOT: SB46.2 SB65.1 U2.24 U7.15 | length 48.6
  Top Layer w0.152: U2.24@49.254,17.825 49.254,18.723 49.428,18.898 49.936,18.898 51.13,17.704 v2(51.13,17.221) ; SB65.1@77.224,13.03 77.368,13.03 v1(77.826,13.487) ; v1(79.858,16.18) v1@79.865,16.172 ; v1@79.916,16.172 v1@80.035,16.172 ; U7.15@80.715,19.51 80.326,19.51 79.865,19.05 v1@79.865,16.172 ; SB46.2@80.968,15.24 80.797,15.24 80.793,15.244 v1@79.865,16.172
  Mid-Layer 1 w0.152: v2(51.13,17.221) 51.13,13.411 v1(53.594,10.947)
  Mid-Layer 2 w0.152: v1(53.594,10.947) 54.559,9.982 64.478,9.982 64.794,9.667 68.659,9.667 71.768,12.776 75.903,12.776 76.69,13.564 79.706,13.564 80.086,13.944 80.086,15.951 v1(79.858,16.18)
IMCU_CTS: TP1.1 U2.38 U5.3 | length 27
  Top Layer w0.152: U2.38@51.329,25.4 52.389,25.4 52.973,25.984 53.67,25.984 58.471,25.984 TP1.1@65.405,19.05 ; TP1.1@65.786,19.05 66.548,18.288 69.266,18.288 70.002,17.551 73.228,17.551 74.139,18.463 U5.3@74.139,18.885
IMCU_RESET: J4.10 R66.1 U2.57 | length 19.4
  Top Layer w0.152: U2.57@46.754,32.975 46.754,33.894 46.457,34.192 46.457,37.717 47.907,39.167 51.773,39.167 R66.1@53.221,40.615 ; R66.1@53.297,40.538 53.831,41.072 55.726,41.072 56.64,40.157 58.572,40.157 J4.10@59.055,40.64
IMCU_RTS: TP3.1 U2.39 U5.15 | length 24.3
  Top Layer w0.152: U2.39@51.329,25.9 52.458,25.9 52.848,26.29 53.035,26.29 56.972,26.29 56.974,26.289 58.597,26.289 64.871,20.015 67.361,20.015 TP3.1@67.988,19.388 ; TP3.1@68.326,19.05 68.786,19.51 U5.15@72.714,19.51
IMCU_RXD: TP2.1 U2.40 U5.11 | length 27.6
  Top Layer w0.152: U2.40@51.329,26.4 52.527,26.4 52.722,26.595 58.722,26.595 63.092,22.225 65.151,22.225 TP2.1@65.786,21.59 66.675,20.701 69.247,20.701 70.695,22.149 71.907,22.149 72.39,22.631 73.355,22.631 73.732,22.254 U5.11@73.732,20.532
IMCU_TCKS: J4.4 R65.1 U2.56 | length 30.9
  Top Layer w0.152: U2.56@47.254,32.975 47.254,33.825 46.761,34.318 46.761,37.59 48.033,38.862 52.531,38.862 53.293,39.624 53.827,39.091 v2@55.397,39.091 ; v2(55.745,37.49) 55.974,37.719 61.87,37.719 62.786,38.635 62.786,42.547 60.884,44.45 J4.4@60.325,44.45
  Mid-Layer 1 w0.152: v2@55.397,39.091 55.397,38.989 55.745,38.641 v2(55.745,37.49)
  other v2: 55.372,39.091
IMCU_TDIS: J4.8 R67.1 U2.51 | length 17.4
  Top Layer w0.152: U2.51@49.754,32.975 49.963,32.766 52.068,32.766 R67.1@52.924,33.622 53.236,33.934 55.296,33.934 57.328,35.966 v2(57.328,37.109) ; v2(57.328,40.716) 57.328,42.241 58.267,43.18 J4.8@59.055,43.18
  Mid-Layer 1 w0.152: v2(57.328,37.109) v2(57.328,40.716)
IMCU_TDOS: J4.6 U2.54 | length 24.6
  Top Layer w0.152: U2.54@48.254,32.975 48.254,33.687 47.371,34.571 47.371,37.338 48.285,38.252 52.578,38.252 53.873,36.957 v2(56.566,36.957) ; v2@56.566,40.767 56.566,41.91 58.166,43.51 58.166,44.831 J4.6@59.055,45.72
  Mid-Layer 1 w0.152: v2(56.566,36.957) v2@56.566,40.767
  other v2: 56.566,40.818
IMCU_TMSS: J4.2 R64.1 U2.55 | length 25.7
  Top Layer w0.152: U2.55@47.754,32.975 47.754,33.756 47.066,34.444 47.066,37.464 48.159,38.557 53.293,38.557 53.827,38.024 61.747,38.024 62.484,38.76 62.484,40.604 61.178,41.91 J4.2@60.325,41.91
IMCU_TXD: TP4.1 U2.41 U5.7 | length 31.1
  Top Layer w0.152: U2.41@51.329,26.9 58.848,26.9 63.218,22.53 67.386,22.53 TP4.1@68.326,21.59 69.705,21.59 71.434,23.319 74.826,23.319 76.251,21.895 76.251,20.566 75.592,19.907 U5.7@75.157,19.907
N\R\F\_\O\N\L\Y\: R3.1 TP22.1 U4.B2 | length 7.9
  Top Layer w0.152: U4.B2@107.544,52.876 107.357,53.063 106.187,53.063 R3.1@105.935,53.315 105.537,52.916 105.537,50.516 107.743,48.311 TP22.1@107.772,48.311
NetC3_2: C3.2 L1.1 U1.H23 | length 2.9
  Top Layer w0.145: U1.H23@117.914,38.617 118.019,38.722 119.384,38.722 119.718,38.388 C3.2@119.723,38.383
  Top Layer w0.3: C3.2@119.718,38.388 L1.1@120.612,38.388
NetC9_1: C9.1 U1.N24 | length 2.9
  Top Layer w0.25: U1.N24@118.414,37.367 118.5,37.367 120.25,35.617 C9.1@120.564,35.617
NetC13_1: C13.1 U1.A18 | length 2.6
  Top Layer w0.25: C13.1@115.839,43.217 115.839,42.2 116.414,41.625 U1.A18@116.414,40.867
NetC17_2: C17.2 SB2.1 X2.1 | length 8.3
  Top Layer w0.152: C17.2@106.385,38.05 106.921,38.05 107.421,38.55 107.421,39.34 106.537,40.224 106.537,42.86 v2(106.995,43.317) ; v2@107.02,43.317 v2@107.045,43.291 ; v2(108.153,43.325) SB2.1@108.585,43.757
  Mid-Layer 1 w0.152: v2@107.104,43.401 108.077,43.401 v2(108.153,43.325)
NetC18_2: C18.2 SB1.1 X2.2 | length 9.6
  Top Layer w0.152: v2(106.121,40.665) 106.24,40.784 106.24,42.983 106.426,43.169 SB1.1@106.426,43.757 ; v2(109.068,39.218) 109.254,39.218 109.921,38.55 X2.2@109.921,38.525 109.921,37.675 C18.2@109.298,37.052
  Mid-Layer 1 w0.152: v2@106.147,40.665 107.594,39.218 v2(109.068,39.218)
NetC20_1: C20.1 U1.AC5 | length 3.6
  Top Layer w0.184: C20.1@111.354,32.614 C20.1@111.354,32.617 ; 112.062,34.608 112.202,34.747 112.254,34.747 112.258,34.743 112.749,34.743 112.755,34.749 113.045,34.749 U1.AC5@113.164,34.867
  Top Layer w0.254: C20.1@111.364,32.617 111.364,33.909 112.112,34.657
NetC27_2: C27.2 R25.2 U2.78 | length 4.1
  Top Layer w0.254: C27.2@32.4,29.608 33.289,29.608 34.081,30.4 U2.78@36.179,30.4
NetC44_2: C44.2 SB30.1 U2.47 | length 4.3
  Top Layer w0.152: U2.47@51.329,29.9 52.214,29.9 52.924,30.609 C44.2@52.924,30.666 54.939,30.666 55.291,30.666 SB30.1@55.296,30.67
NetC46_1: C46.1 J5.2 R44.1 TP17.1 | length 12.9
  Top Layer w0.25: TP17.1@123.479,18.44 124.198,18.44 ; J5.2@124.198,9.328 124.198,18.44 ; R44.1@124.198,21.463 124.198,18.44
NetC47_2: C47.2 J5.4 R46.1 TP18.1 | length 12.8
  Top Layer w0.25: J5.4@125.198,9.328 125.198,18.44 ; R46.1@125.198,21.463 125.198,18.44 ; TP18.1@125.909,18.44 125.198,18.44
NetC49_1: C49.1 L6.2 L9.1 | length 1.8
  Top Layer w0.3: C49.1@139.049,56.523 L9.1@140.294,57.768
NetC49_2: C49.2 J1.3 | length 3.1
  Top Layer w0.3: J1.3@137.313,53.052 137.313,54.376 cw(c138.305,54.376) 137.603,55.078 C49.2@138.342,55.816
NetC55_2: C55.2 R34.2 U9.17 | length 6.6
  Top Layer w0.203: R34.2@123.856,45.024 C55.2@123.856,44.197 v2(124.372,44.197) ; U9.17@126.128,40.005 v2(126.128,40.557)
  Mid-Layer 1 w0.203: v2(124.372,44.197) 125.003,44.197 125.461,43.739 125.461,42.803 126.128,42.136 v2(126.128,40.557)
NetC59_2: C59.2 R5.2 U9.19 | length 4.8
  Top Layer w0.203: R5.2@123.856,43.369 C59.2@123.856,42.543 123.856,40.794 125.27,39.38 U9.19@125.503,39.38
NetC60_2: C60.2 C61.2 C62.2 D60.4 FB60.1 J3.1 TP15.1 | length 23
  Top Layer w0.508: FB60.1@84.106,6.866 85.224,6.866 85.471,7.113 v1(88,7.113) 88.429,6.684 J3.1@88.429,6.232 ; v1(88.798,13.894) TP15.1@91.034,16.129 ; D60.4@90.452,11.29 91.047,11.29 91.733,10.603 C61.2@92.623,10.603 v1(92.623,9.728)
  Mid-Layer 2 w0.508: v1(88,7.113) 89.102,7.113 91.717,9.728 v1(92.623,9.728)
  Bottom Layer w0.508: v1(88.798,13.894) 92.623,10.069 v1(92.623,9.728)
NetC63_1: C63.1 C64.2 C65.2 D61.4 FB61.1 J2.1 TP11.1 | length 36.3
  Top Layer w0.508: C64.2@9.144,28.905 D61.4@9.144,31.055
  Top Layer w0.762: v1(2.794,36.373) 5.781,36.373 6.06,36.093 ; J2.1@4.318,33.233 5.41,33.233 6.06,33.884 6.06,35.56 ; v1(4.496,24.232) 4.496,25.538 6.86,27.902 8.217,27.902 C64.2@9.297,28.981 ; FB61.1@6.06,37.734 6.06,36.093 ; TP11.1@10.16,35.56 6.06,35.56 ; 6.06,35.56 6.06,36.093
  Mid-Layer 2 w0.762: v1(2.794,36.373) 5.004,34.163 5.004,24.74 v1(4.496,24.232)
NetC66_2: C66.2 FB64.1 J3.6@86.429,3.557 J3.6@86.529,6.007 J3.6@88.529,3.557 J3.6@90.929,3.557 J3.6@92.929,6.007 J3.6@93.029,3.557 R62.2 | length 14.7
  Top Layer w0.508: J3.6@86.427,6.003 86.427,3.653 J3.6@93.027,3.653 ; J3.6@93.027,3.399 cw(c93.331,3.399) J3.6@93.029,3.434 ; J3.6@93.029,3.303 J3.6@93.029,3.434 ; J3.6@93.029,3.688 J3.6@93.029,6.003 ; J3.6@93.331,3.703 ccw(c93.331,3.399) J3.6@93.029,3.434 ; J3.6@93.331,3.83 FB64.1@96.12,3.83
NetC67_2: C67.2 FB65.1 J2.6@1.944,28.45 J2.6@1.944,30.55 J2.6@1.944,32.95 J2.6@1.944,35.05 J2.6@4.394,28.55 J2.6@4.394,34.95 R63.2 | length 15.1
  Top Layer w0.508: FB65.1@1.546,25.139 1.546,27.378 1.944,27.776 J2.6@1.944,28.45 ; J2.6@2.087,28.434 J2.6@2.071,28.45 ; J2.6@4.521,28.55 4.421,28.45 J2.6@2.071,28.45 ; J2.6@4.521,34.95 4.421,35.05 2.071,35.05 J2.6@2.071,28.45
NetC72_2: C72.2 L8.1 U9.8 | length 2.3
  Top Layer w0.3: U9.8@128.753,37.88 L8.1@131.025,37.88
NetC73_2: C73.2 J1.1 L8.2 | length 16.3
  Top Layer w0.3: L8.2@132.087,37.868 133.092,37.868 C73.2@133.096,37.872 ccw(c133.096,42.089) 137.313,42.089 J1.1@137.313,50.732
NetC74_2: C74.2 R33.2 U9.15 | length 8.4
  Top Layer w0.203: R33.2@123.856,46.678 C74.2@123.856,45.851 v7(124.511,45.851) ; U9.15@127.128,40.005 v2@127.128,40.512
  Mid-Layer 1 w0.203: v7(124.511,45.851) 124.511,45.559 125.926,44.144 125.926,42.969 127.127,41.768 v2(127.127,40.513)
NetC75_2: C75.2 L10.1 U9.6 | length 2.1
  Top Layer w0.3: C75.2@128.128,36.207 U9.6@128.128,37.255 ; C75.2@128.275,36.043 128.275,35.933 ccw(c129.449,35.933) L10.1@128.619,35.103
NetC76_2: C76.2 J7.1 L10.2 | length 24.3
  Top Layer w0.3: L10.2@129.326,34.396 134.093,29.629 cw(c127.91,23.446) 136.654,23.446 J7.1@136.654,12.731
NetC77_2: C77.2 R8.2 U9.2 | length 7.9
  Top Layer w0.203: U9.2@126.128,37.255 126.128,31.69 125.696,31.259 C77.2@125.696,30.358 126.501,30.358 R8.2@126.526,30.383
NetC78_2: C78.2 R9.2 U9.3 | length 8
  Top Layer w0.203: U9.3@126.628,37.255 126.628,31.259 127.356,30.531 C78.2@127.356,30.358 127.381,30.383 R9.2@128.185,30.383
NetC79_2: C79.2 R10.2 U9.4 | length 8.5
  Top Layer w0.203: U9.4@127.128,37.255 127.128,32.383 129.015,30.495 C79.2@129.015,30.358 129.82,30.358 R10.2@129.845,30.383
NetC81_1: C81.1 R80.1 R81.2 U12.7 | length 7.2
  Top Layer w0.254: C81.1@6.045,25.544 R80.1@6.934,25.544 ; R80.1@6.934,25.519 R80.1@6.934,25.544 ; R81.2@7.849,25.179 7.484,25.544 R80.1@6.934,25.544 ; U12.7@11.074,26.914 7.381,26.914 6.934,26.467 R80.1@6.934,25.544
NetC84_2: C84.2 U12.3 | length 2.8
  Top Layer w0.254: U12.3@13.614,26.414 14.175,26.414 14.427,26.666 14.427,27.936 14.685,28.194 C84.2@14.918,28.194
NetC86_2: C86.2 D84.3 U11.4 U11.6 | length 10.3
  Top Layer w0.25: 21.856,21.184 21.857,21.182 21.871,21.168
  Top Layer w0.254: U11.4@21.701,19.718 22.284,19.718 22.657,20.091 22.657,21.031 22.352,21.336 21.857,21.336
  Top Layer w0.508: D84.3@19.507,27.268 20.862,25.914 20.862,24.477 21.857,23.482 C86.2@21.857,22.784 ; 21.857,20.906 21.857,21.182 21.857,21.336 C86.2@21.857,22.76
NetC87_1: C87.1 R82.1 R84.2 U11.3 | length 3.6
  Top Layer w0.152: R82.1@19.55,18.085 R82.1@19.575,18.085 ; C87.1@19.575,17.17 R82.1@19.575,18.085 ; U11.3@19.751,19.718 19.575,19.542 R82.1@19.575,18.085 ; R84.2@20.506,18.085 R82.1@19.575,18.085
NetC92_2: C92.2 SB81.2 SW9.7 U23.5 | length 26.8
  Top Layer w0.762: SW9.7@25.749,39.906 25.749,38.996 26.213,38.532 29.769,38.532 v1(30.734,39.497) ; v1(45.796,39.802) 47.473,39.802 48.51,40.839 ; U23.5@48.51,41.123 48.51,40.839 ; 49.387,39.963 48.51,40.839
  Mid-Layer 2 w1.016: v1(30.734,39.497) 31.623,40.386 45.212,40.386 v1(45.796,39.802)
NetC94_2: C94.2 R12.2 R13.2 TP48.1 | length 3.8
  Top Layer w0.203: R12.2@126.683,59.475 128.974,59.475 R13.2@128.999,59.5 128.999,58.603 TP48.1@129.422,58.179
NetC96_2: C96.2 L5.2 SB28.2 U10.B2 | length 4.7
  Top Layer w0.203: U10.B2@113.497,60.3 114.715,60.3 C96.2@114.717,60.302
  Top Layer w0.381: L5.2@113.994,61.837 114.348,61.483 114.348,60.302 C96.2@114.717,60.302 SB28.2@116.147,60.302
NetC98_2: C98.2 C99.2 R15.2 SB27.2 U26.5 | length 4.6
  Top Layer w0.254: U26.5@128.598,52.542 128.321,52.264 128.321,51.855 R15.2@127.716,51.25 127.691,51.225 C98.2@127.691,50.387 C99.2@127.691,49.523 127.698,49.53 128.697,49.53 SB27.2@128.872,49.53
NetC101_1: C101.1 L7.2 L11.1 | length 1.8
  Top Layer w0.3: C101.1@139.023,6.951 L11.1@140.268,5.706
NetC101_2: C101.2 J7.3 | length 3.3
  Top Layer w0.3: J7.3@136.654,10.411 136.654,10.373 ccw(c139.194,10.373) 137.398,8.577 C101.2@138.316,7.658
NetFB62_1: FB62.1 J3.5 TP16.1 | length 13.2
  Top Layer w0.508: J3.5@91.029,5.978 91.029,6.803 93.614,9.387 FB62.1@93.614,11.083 94.457,11.083 97.104,13.73 TP16.1@97.104,16.129
NetFB63_1: FB63.1 J2.5 | length 1.8
  Top Layer w0.381: J2.5@4.619,30.45 4.737,30.45 FB63.1@5.933,29.254
NetL2_1: L2.1 L3.2 | length 1.1
  Top Layer w0.25: L2.1@110.914,43.942 L3.2@110.914,44.992
NetL2_2: L2.2 U1.B3 | length 2.9
  Top Layer w0.25: L2.2@110.914,42.592 110.914,42.117 U1.B3@112.664,40.367
NetL4_2: L4.2 U1.AB2 | length 3.1
  Top Layer w0.203: 111.957,35.063 111.98,35.087 112.383,35.087 U1.AB2@112.414,35.117
  Top Layer w0.25: L4.2@110.189,33.342 L4.2@110.236,33.342 ; L4.2@110.33,33.342 L4.2@110.236,33.342 ; 111.957,35.063 L4.2@110.236,33.342
NetL5_1: L5.1 U10.B1 | length 1.9
  Top Layer w0.203: L5.1@112.644,61.837 112.644,60.508 112.852,60.3 U10.B1@113.097,60.3
NetL80_1: L80.1 U12.2 | length 3
  Top Layer w0.457: U12.2@13.614,25.764 14.283,25.764 15.553,27.033 L80.1@16.104,27.033
NetL81_1: L81.1 U11.1 | length 2.6
  Top Layer w0.508: L81.1@17.399,21.649 19.151,21.649 19.751,21.048
NetLED1_1: LED1.1 SB5.2 | length 12.4
  Top Layer w0.152: LED1.1@110.575,53.917 112.48,55.822 119.979,55.822 120.965,54.837 120.965,54.696 SB5.2@121.464,54.197
NetLED1_2: LED1.2 R47.1 | length 1.1
  Top Layer w0.254: LED1.2@111.972,53.917 112.932,53.917 R47.1@113.059,54.044
NetLED2_1: LED2.1 SB6.2 | length 5
  Top Layer w0.152: LED2.1@116.925,53.917 118.067,52.774 120.968,52.774 SB6.2@121.464,52.774
NetLED2_2: LED2.2 R48.1 | length 1.1
  Top Layer w0.254: LED2.2@118.322,53.917 119.257,53.917 R48.1@119.384,54.044
NetLED3_1: LED3.1 SB7.2 | length 12.2
  Top Layer w0.152: LED3.1@110.575,50.107 112.766,52.299 120.517,52.299 SB7.2@121.464,51.352
NetLED3_2: LED3.2 R50.1 | length 1.1
  Top Layer w0.254: LED3.2@111.972,50.107 112.932,50.107 R50.1@113.059,50.234
NetLED4_1: LED4.1 SB8.2 | length 5.5
  Top Layer w0.152: LED4.1@116.925,50.107 118.042,48.99 120.643,48.99 121.464,49.81 SB8.2@121.464,49.93
NetLED4_2: LED4.2 R51.1 | length 1.1
  Top Layer w0.254: LED4.2@118.322,50.107 119.257,50.107 R51.1@119.384,50.234
NetLED5_1: LED5.1 R20.1 | length 1.8
  Top Layer w0.254: R20.1@32.636,17.747 LED5.1@32.636,19.57
NetLED5_2: LED5.2 R21.1 | length 1.8
  Top Layer w0.254: R21.1@33.486,17.747 LED5.2@33.486,19.57
NetP1_3: P1.3 P5.5 P7.3 P11.5 P13.6 SB43.2 SB44.1 U7.4 | length 115
  Top Layer w0.152: P1.3@33.02,9.085 33.02,9.906 33.807,10.693 37.023,10.693 38.506,12.177 49.748,12.177 v1(52.095,9.83) ; P5.5@62.679,30.485 v1(62.679,31.506) 67.6,31.506 68.174,32.08 70.002,32.08 71.044,31.039 78.237,31.039 79.152,31.953 v1(81.356,31.953) ; SB43.2@81.592,16.764 81.592,17.117 81.592,17.356 v2@81.737,17.501 ; U7.4@82.54,18.885 82.54,18.399 v1(83.033,17.907) 85.724,17.907 87.091,19.275 88.675,19.275 89.259,19.859 SB44.1@89.408,20.008 ; SB44.1@89.366,20.049 89.459,20.142
  Top Layer w0.381: P13.6@33.02,3.81 P1.3@33.02,6.155 v1(33.02,7.62) P1.3@33.02,9.085
  Mid-Layer 1 w0.152: v2@81.737,17.501 82.144,17.907 v1(83.033,17.907)
  Mid-Layer 2 w0.152: v1(52.095,9.83) 52.248,9.677 64.352,9.677 64.667,9.362 68.785,9.362 71.894,12.471 82.728,12.471 83.033,12.776 v1(83.033,17.907) 83.033,21.608 82.803,21.837 82.803,30.506 v1(81.356,31.953)
  Bottom Layer w0.152: P11.5@62.679,30.48 v1(62.679,31.506)
  Bottom Layer w0.381: P7.3@33.02,6.155 v1(33.02,7.62) P7.3@33.02,9.085
  other v2: 81.712,17.501
NetP2_6: P2.6 P8.6 P14.12 SB17.2 TP47.1 | length 61.9
  Top Layer w0.152: TP47.1@99.695,27.686 99.873,27.864 v1(99.873,28.854) 100.907,28.854 101.6,29.548 101.6,30.086 SB17.2@101.6,30.26
  Top Layer w0.381: P14.12@63.5,3.81 P2.6@63.5,6.155 v1(63.5,7.62) P2.6@63.5,9.085
  Mid-Layer 2 w0.152: v1(63.5,7.62) 63.587,7.533 69.543,7.533 72.652,10.643 89.28,10.643 96.986,18.348 96.986,21.521 98.425,22.96 98.425,26.836 99.873,28.284 v1(99.873,28.854)
  Bottom Layer w0.381: P8.6@63.5,6.155 v1(63.5,7.62) P8.6@63.5,9.085
NetP3_8: P3.8 P9.8 P15.16 SB26.2 | length 80.1
  Top Layer w0.152: P3.8@45.72,54.415 45.72,53.543 45.872,53.391 47.339,53.391 49.777,50.952 81.609,50.952 87.147,45.414 87.147,37.668 86.919,37.44 v1(86.919,37.135) ; v1(100.672,41.555) SB26.2@101.276,41.555
  Top Layer w0.381: P3.8@45.72,54.415 v1(45.72,55.88) P3.8@45.72,57.345 P15.16@45.72,59.69
  Bottom Layer w0.152: v1(86.919,37.135) 87.628,36.426 97.31,36.426 98.984,38.1 98.984,39.867 v1(100.672,41.555)
  Bottom Layer w0.381: P9.8@45.72,54.415 v1(45.72,55.88) P9.8@45.72,57.345
NetP5_6: P5.6 P11.6 SB32.2 SB33.1 | length 5.2
  Top Layer w0.152: SB33.1@66.378,27.94 67.077,27.94 ; P5.6@67.119,30.48 67.252,30.348 67.252,28.293 SB32.2@67.252,27.94
  Top Layer w0.254: P5.6@68.555,30.531 v1(68.555,31.481)
  Bottom Layer w0.254: P11.6@68.555,30.531 v1(68.555,31.481)
NetP6_7: P6.7 P12.7 P17.14 R43.1 | length 98.9
  Top Layer w0.152: v1(123.165,24.886) 123.165,23.796 R43.1@123.169,23.8
  Top Layer w0.381: P6.7@71.12,54.415 v1(71.12,55.88) P6.7@71.12,57.345 P17.14@71.12,59.69
  Mid-Layer 2 w0.152: v1(71.12,55.88) 71.12,53.417 74.473,50.064 74.473,41.631 70.536,37.694 70.536,35.822 71.882,34.475 71.882,26.416 v1(71.628,26.162)
  Bottom Layer w0.152: v1(71.628,26.162) 72.161,26.695 82,26.695 86.445,22.25 87.729,22.25 90.571,25.092 92.648,25.092 93.413,25.857 96.073,25.857 97.089,24.841 111.658,24.841 ; 111.658,24.845 112.518,25.704 118.721,25.704 119.331,25.093 122.957,25.093 v1(123.165,24.886)
  Bottom Layer w0.381: P12.7@71.12,54.415 v1(71.12,55.88) P12.7@71.12,57.345
NetP6_8: P6.8 P12.8 P17.16 R45.1 | length 102.2
  Top Layer w0.152: v1(126.242,24.886) 126.242,23.809 R45.1@126.251,23.8
  Top Layer w0.381: P6.8@68.58,54.415 v1(68.58,55.88) P6.8@68.58,57.345 P17.16@68.58,59.69
  Mid-Layer 2 w0.152: v1(68.58,55.88) 68.58,55.526 74.168,49.938 74.168,41.758 70.231,37.821 70.231,35.695 71.577,34.349 71.577,27.356 v1(71.222,27)
  Bottom Layer w0.152: 71.425,27 82.126,27 86.571,22.555 87.603,22.555 90.445,25.397 92.521,25.397 93.287,26.162 96.196,26.162 97.212,25.146 111.532,25.146 112.392,26.006 118.849,26.006 119.435,25.42 125.707,25.42 v1(126.242,24.886)
  Bottom Layer w0.381: P12.8@68.58,54.415 v1(68.58,55.88) P12.8@68.58,57.345
NetP20_12: P20.12 P26.12 | length 5.9
  Top Layer w0.762: P20.12@46.736,44.255 P20.12@46.736,47.185
  Bottom Layer w0.762: P26.12@46.736,44.255 v1(46.736,45.72) P26.12@46.736,47.185
NetP21_2: P21.2 SW10.2 SW10.4 TP27.1 | length 23.4
  Top Layer w0.508: P21.2@11.811,18.009 12.852,16.967 12.852,15.316 v1(12.802,15.265) ; v1(17.831,6.248) 17.831,5.004 18.212,4.623 20.574,4.623 ; SW10.2@20.625,5.914 20.625,4.674 20.574,4.623 ; SW10.4@22.375,2.214 22.375,2.822 20.574,4.623
  Bottom Layer w0.508: v1(12.802,15.265) 13.64,15.265 13.919,14.986 13.919,14.305 17.78,10.444 17.78,6.299 v1(17.831,6.248)
NetP24_7: P24.7 SB23.2 | length 60
  Top Layer w0.152: P24.7@93.027,45.72 93.624,45.72 v1(94.844,46.939) ; v1(104.445,21.336) 105.225,21.336 108.374,18.186 109.932,18.186 111.075,19.329 119.076,19.329 120.581,20.835 SB23.2@120.581,21.768
  Mid-Layer 2 w0.152: v1(94.369,21.107) 94.251,21.107 93.531,21.827 93.531,22.811 93.396,22.947 93.396,25.909 94.463,26.976 94.463,40.107 95.606,41.25 95.606,43.365 94.717,44.254 94.717,44.722 94.742,44.747 94.742,46.838 v1(94.844,46.939)
  Bottom Layer w0.152: v1(94.369,21.107) 95.327,21.107 95.784,20.65 103.231,20.65 103.917,21.336 v1(104.445,21.336)
NetP24_9: P24.9 SB21.2 | length 41.3
  Top Layer w0.152: P24.9@93.027,43.18 94.323,44.475 v1(95.25,44.475) ; v1(104.445,22.403) 106.191,22.403 106.78,22.992 106.78,23.831 107.108,24.159 SB21.2@107.257,24.308
  Mid-Layer 2 w0.152: v1(94.369,22.174) 94.369,22.835 94.005,23.199 94.005,25.656 95.072,26.723 95.072,38.768 95.91,39.606 95.91,43.815 v1(95.25,44.475)
  Bottom Layer w0.152: v1(94.369,22.174) 95.149,22.174 96.064,21.26 102.979,21.26 104.122,22.403 v1(104.445,22.403)
NetP24_10: P24.10 SB22.2 | length 40.2
  Top Layer w0.152: v1(96.114,44.475) 96.177,44.475 P24.10@97.472,43.18 ; v1(105.004,22.936) 106.293,22.936 106.475,23.118 106.475,23.957 106.78,24.262 106.78,25.101 107.108,25.429 SB22.2@107.257,25.578
  Mid-Layer 2 w0.152: v1(94.928,22.708) 94.31,23.326 94.31,25.53 95.377,26.597 95.377,38.642 96.215,39.48 96.215,44.374 v1(96.114,44.475)
  Bottom Layer w0.152: v1(94.928,22.708) 95.047,22.708 96.19,21.565 102.852,21.565 104.224,22.936 v1(105.004,22.936)
NetP24_11: P24.11 SB24.2 | length 57.2
  Top Layer w0.152: P24.11@93.027,40.64 93.904,40.64 v1(94.92,41.656) ; v1(105.004,20.803) 105.327,20.803 108.248,17.882 110.058,17.882 111.201,19.025 119.202,19.025 121.049,20.872 121.049,22.461 120.472,23.038
  Mid-Layer 2 w0.152: v1(94.92,41.656) 94.158,40.894 94.158,27.102 93.091,26.035 93.091,23.335 92.456,22.7 92.456,22.233 94.115,20.574 v1(94.928,20.574)
  Bottom Layer w0.152: v1(94.928,20.574) 95.429,20.574 95.658,20.345 103.357,20.345 103.814,20.803 v1(105.004,20.803)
